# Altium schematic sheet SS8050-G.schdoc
size 127 x 101 mm
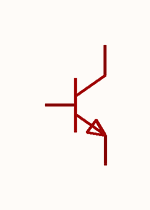
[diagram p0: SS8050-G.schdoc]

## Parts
Q?  ss8050-g(range:120-200)  [SOT-23-3_L2.9-W1.3-P1.90-LS2.4-BR]  (value not drawn)

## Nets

Not connected (* = marked no-connect by the designer): Q? 1(B) 2(E) 3(C)

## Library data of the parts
Q? = ss8050-g(range:120-200): 晶体管类型:NPN;集电极电流(Ic):1.5A;集射极击穿电压(Vceo):25V;耗散功率(Pd):300mW;直流电流增益(hFE):120;; Manufacturer: CJ(江苏长电/长晶); AddInBom: yes; ModelId: c62791f0466c4ae2a892c056b845b0ca; ModelName: SOT-23-3P_L2.9-W1.3-H1.0-LS2.4-P0.95; ModelTransform: 98.425,114.173,0,180,0,0,0.0005,-0.0005,0; type: NPN; Current - Collector(Ic): 1.5A; Collector - Emitter Voltage VCEO: 25V; Pd - Power Dissipation: 300mW; DC Current Gain: 120; Transition frequency(fT): 100MHz; Current - Collector Cutoff: 100nA; Vce Saturation(VCE(sat)): 500mV; Emitter-Base Voltage(Vebo): 5V; Number: 1个NPN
